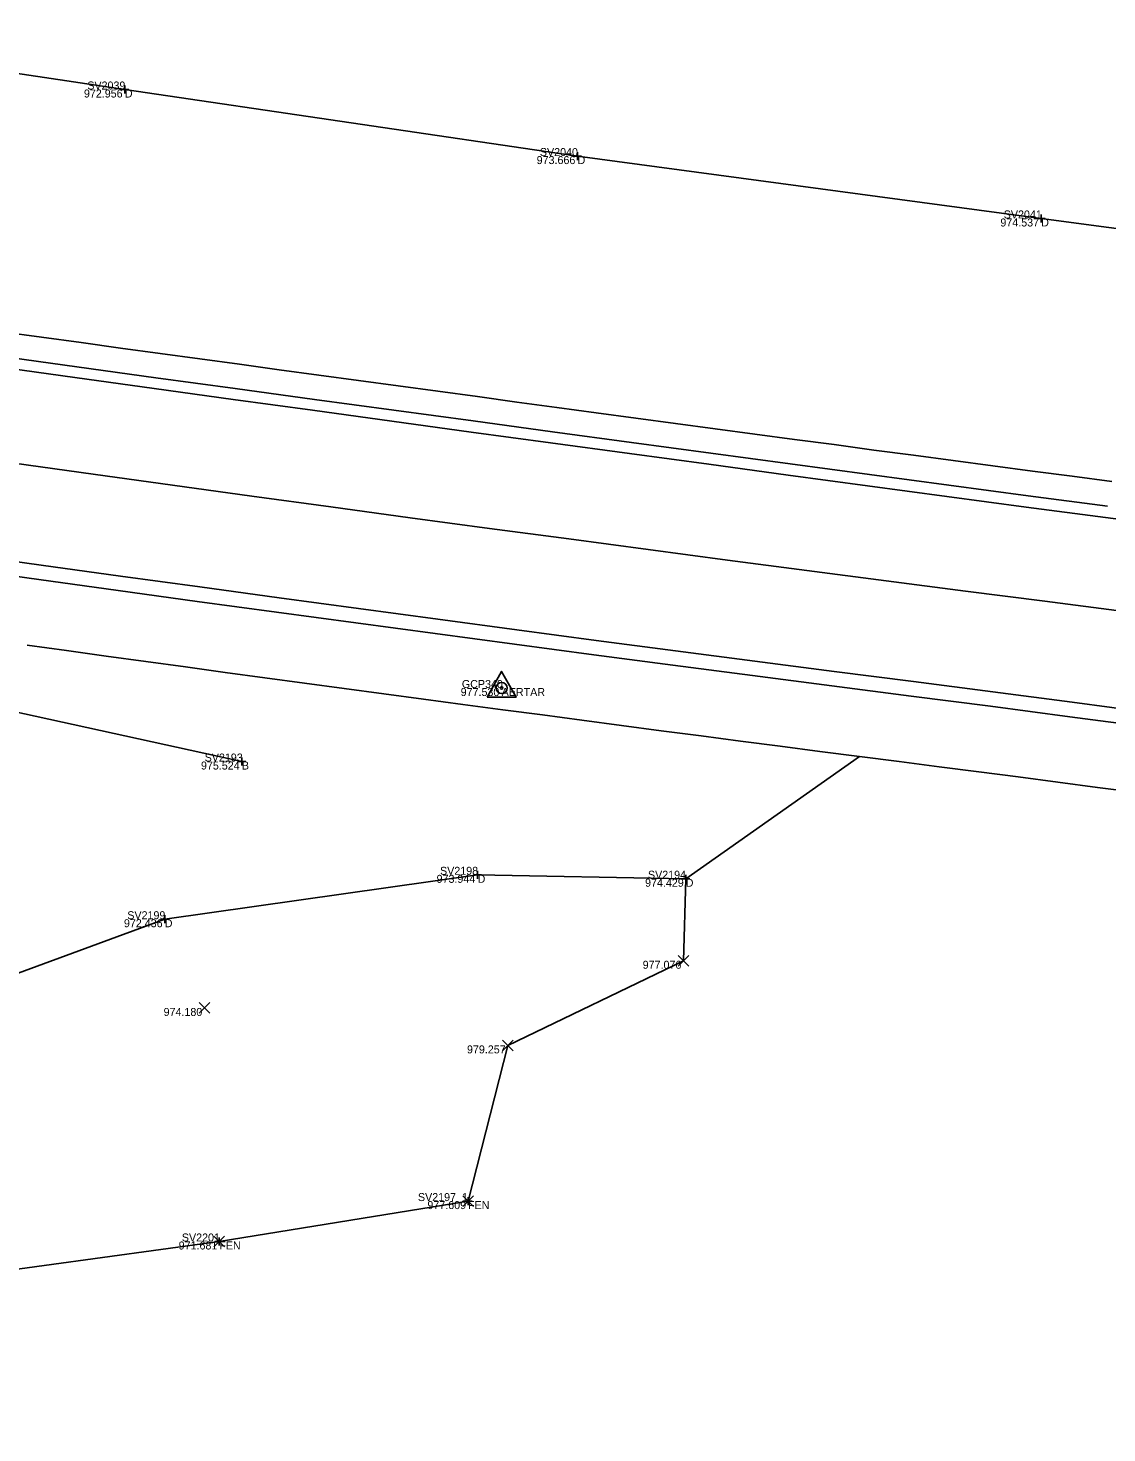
# Model space of a CAD drawing. Extents: x 2065431 to 2068157, y 709104 to 709719.
# Drawn here: x 2066585.2 to 2066720, y 709278 to 709453.6 of the extents above; entities that cross this region are included whole.
import ezdxf

# ---------------------------------------------------------------- set-up
doc = ezdxf.new("R2010")
doc.units = 0
for name, color, linetype in [('DT_X_Terrain_Boundary', 7, 'Continuous'), ('PM_X_Edge_Line', 7, 'Continuous'), ('PM_X_Lane_Line', 7, 'Continuous'), ('PV_X_EOP', 7, 'Continuous'), ('PV_X_Shoulder_Rumble_Strip', 7, 'Continuous'), ('RD_X_Fence', 7, 'Continuous'), ('RS_Raster1', 7, 'Continuous'), ('RW_X_CL_100_Bearings', 7, 'Continuous'), ('RW_X_Fee_WL', 7, 'Continuous'), ('SV_P_Aerial_Targets', 7, 'Continuous'), ('SV_X_Break_Lines', 7, 'Continuous'), ('SV_X_Mon_Cells_Found', 7, 'Continuous'), ('SV_X_Text_Elevation', 7, 'Continuous'), ('SV_X_Text_Name', 7, 'Continuous')]:
    doc.layers.add(name, color=color, linetype=linetype)

msp = doc.modelspace()

# ---------------------------------------------------------------- linework, layer by layer
at = {"layer": 'DT_X_Terrain_Boundary'}
msp.add_lwpolyline([(2066536.08, 709291.94), (2066609.07, 709301.93), (2066640.16, 709306.98), (2066645.12, 709326.44), (2066667.1, 709337.02), (2066667.37, 709347.27), (2066689.11, 709362.55), (2066694.07, 709361.91), (2066699.03, 709361.27), (2066703.99, 709360.64), (2066708.94, 709359.99), (2066713.9, 709359.34), (2066718.86, 709358.69), (2066723.82, 709358.04)], dxfattribs=at)
at = {"layer": 'PM_X_Edge_Line'}
for points in [[(2066581.1, 709411.28), (2066591.01, 709409.91), (2066600.91, 709408.54), (2066610.82, 709407.18), (2066620.73, 709405.82), (2066630.63, 709404.46), (2066640.54, 709403.11), (2066650.45, 709401.76), (2066660.36, 709400.41), (2066670.27, 709399.07), (2066680.18, 709397.72), (2066690.09, 709396.39), (2066700, 709395.05), (2066709.91, 709393.73), (2066719.82, 709392.43), (2066729.74, 709391.14)], [(2066576.92, 709387.84), (2066586.82, 709386.47), (2066596.73, 709385.1), (2066606.64, 709383.74), (2066616.55, 709382.39), (2066626.46, 709381.05), (2066636.37, 709379.71), (2066646.28, 709378.39), (2066656.19, 709377.07), (2066666.11, 709375.77), (2066676.02, 709374.47), (2066685.94, 709373.19), (2066695.86, 709371.91), (2066705.77, 709370.63), (2066715.69, 709369.33), (2066725.6, 709368.02)]]:
    msp.add_lwpolyline(points, dxfattribs=at)
at = {"layer": 'PM_X_Lane_Line'}
msp.add_lwpolyline([(2066583.41, 709399.22), (2066593.31, 709397.84), (2066603.22, 709396.47), (2066613.13, 709395.1), (2066623.03, 709393.75), (2066632.94, 709392.4), (2066642.85, 709391.06), (2066652.76, 709389.74), (2066662.68, 709388.42), (2066672.59, 709387.11), (2066682.51, 709385.81), (2066692.42, 709384.51), (2066702.34, 709383.23), (2066712.26, 709381.96), (2066722.18, 709380.69)], dxfattribs=at)
at = {"layer": 'PV_X_EOP'}
for points in [[(2066581.88, 709415.65), (2066586.83, 709414.97), (2066591.79, 709414.29), (2066596.74, 709413.61), (2066601.69, 709412.93), (2066606.65, 709412.25), (2066611.6, 709411.57), (2066616.56, 709410.9), (2066621.51, 709410.22), (2066626.46, 709409.55), (2066631.42, 709408.87), (2066636.37, 709408.2), (2066641.33, 709407.53), (2066646.28, 709406.86), (2066651.24, 709406.19), (2066656.19, 709405.52), (2066661.15, 709404.85), (2066666.1, 709404.18), (2066671.06, 709403.52), (2066676.01, 709402.85), (2066680.97, 709402.19), (2066685.93, 709401.53), (2066690.88, 709400.86), (2066695.84, 709400.2), (2066700.79, 709399.54), (2066705.75, 709398.88), (2066710.71, 709398.23), (2066715.67, 709397.58), (2066720.62, 709396.93)], [(2066585.04, 709376.47), (2066589.99, 709375.79), (2066594.94, 709375.1), (2066599.9, 709374.42), (2066604.85, 709373.74), (2066609.8, 709373.07), (2066614.76, 709372.39), (2066619.71, 709371.72), (2066624.67, 709371.05), (2066629.62, 709370.38), (2066634.58, 709369.72), (2066639.53, 709369.06), (2066644.49, 709368.39), (2066649.45, 709367.74), (2066654.4, 709367.08), (2066659.36, 709366.43), (2066664.32, 709365.77), (2066669.28, 709365.12), (2066674.23, 709364.48), (2066679.19, 709363.83), (2066684.15, 709363.19), (2066689.11, 709362.55), (2066694.07, 709361.91), (2066699.03, 709361.27), (2066703.99, 709360.64), (2066708.94, 709359.99), (2066713.9, 709359.34), (2066718.86, 709358.69), (2066723.82, 709358.04)]]:
    msp.add_lwpolyline(points, dxfattribs=at)
at = {"layer": 'PV_X_Shoulder_Rumble_Strip'}
for points in [[(2066581.34, 709412.62), (2066591.25, 709411.26), (2066601.15, 709409.9), (2066611.06, 709408.54), (2066620.97, 709407.19), (2066630.88, 709405.84), (2066640.79, 709404.49), (2066650.7, 709403.14), (2066660.61, 709401.8), (2066670.52, 709400.46), (2066680.43, 709399.13), (2066690.34, 709397.8), (2066700.25, 709396.47), (2066710.16, 709395.15), (2066720.08, 709393.85)], [(2066576.6, 709386.04), (2066586.5, 709384.66), (2066596.41, 709383.29), (2066606.31, 709381.93), (2066616.22, 709380.58), (2066626.13, 709379.24), (2066636.04, 709377.91), (2066645.96, 709376.58), (2066655.87, 709375.27), (2066665.78, 709373.96), (2066675.7, 709372.67), (2066685.62, 709371.38), (2066695.53, 709370.1), (2066705.45, 709368.83), (2066715.37, 709367.52), (2066725.28, 709366.22)]]:
    msp.add_lwpolyline(points, dxfattribs=at)
at = {"layer": 'RD_X_Fence'}
msp.add_lwpolyline([(2066428.96, 709278), (2066457.85, 709280.4), (2066536.08, 709291.94), (2066609.07, 709301.93), (2066640.16, 709306.98)], dxfattribs=at)
at = {"layer": 'RS_Raster1'}
for p, q in [((2066596.76, 709445.92), (2066597.76, 709445.92)), ((2066597.26, 709446.42), (2066597.26, 709445.42)), ((2066597.26, 709445.92), (2066597.26, 709445.92)), ((2066653.85, 709438.1), (2066653.85, 709437.1)), ((2066653.35, 709437.6), (2066654.35, 709437.6)), ((2066653.85, 709437.6), (2066653.85, 709437.6)), ((2066711.3, 709429.8), (2066712.3, 709429.8)), ((2066711.8, 709430.3), (2066711.8, 709429.3)), ((2066711.8, 709429.8), (2066711.8, 709429.8)), ((2066611.9, 709362.42), (2066611.9, 709361.42)), ((2066611.4, 709361.92), (2066612.4, 709361.92)), ((2066611.9, 709361.92), (2066611.9, 709361.92)), ((2066640.86, 709347.76), (2066641.86, 709347.76)), ((2066641.36, 709348.26), (2066641.36, 709347.26)), ((2066641.36, 709347.76), (2066641.36, 709347.76)), ((2066666.87, 709347.27), (2066667.87, 709347.27)), ((2066667.37, 709347.77), (2066667.37, 709346.77)), ((2066667.37, 709347.27), (2066667.37, 709347.27)), ((2066601.75, 709342.21), (2066602.75, 709342.21)), ((2066602.25, 709342.71), (2066602.25, 709341.71)), ((2066602.25, 709342.21), (2066602.25, 709342.21)), ((2066639.66, 709306.98), (2066640.66, 709306.98)), ((2066640.16, 709307.48), (2066640.16, 709306.48)), ((2066640.16, 709306.98), (2066640.16, 709306.98)), ((2066608.57, 709301.93), (2066609.57, 709301.93)), ((2066609.07, 709302.43), (2066609.07, 709301.43)), ((2066609.07, 709301.93), (2066609.07, 709301.93))]:
    msp.add_line(p, q, dxfattribs=at)
at = {"layer": 'RW_X_CL_100_Bearings'}
for p, q in [((2066666.43, 709336.35), (2066667.76, 709337.69)), ((2066666.43, 709337.69), (2066667.76, 709336.35)), ((2066606.56, 709330.46), (2066607.89, 709331.79)), ((2066606.56, 709331.79), (2066607.89, 709330.46)), ((2066644.46, 709325.78), (2066645.79, 709327.11)), ((2066644.46, 709327.11), (2066645.79, 709325.78)), ((2066639.49, 709306.32), (2066640.83, 709307.65)), ((2066639.49, 709307.65), (2066640.83, 709306.32)), ((2066608.4, 709301.26), (2066609.74, 709302.6)), ((2066608.4, 709302.6), (2066609.74, 709301.26))]:
    msp.add_line(p, q, dxfattribs=at)
at = {"layer": 'RW_X_Fee_WL'}
for points in [[(2066146.22, 709516.28), (2066201.46, 709507.43), (2066256.41, 709499.89), (2066309.66, 709487.73), (2066371.95, 709478.62), (2066434.46, 709468.76), (2066488.47, 709461.11), (2066543.09, 709454.02), (2066597.26, 709445.92), (2066653.85, 709437.6), (2066711.8, 709429.8), (2066769.12, 709422.19), (2066823.53, 709415.48), (2066878.43, 709408.48), (2066947.7, 709399.97)], [(2066667.37, 709347.27), (2066641.36, 709347.76), (2066602.25, 709342.21), (2066565.56, 709328.7), (2066528.33, 709316.01), (2066473.21, 709304.82), (2066473.18, 709304.77), (2066439.48, 709297.22), (2066426.74, 709291.84), (2066416.55, 709290.35)]]:
    msp.add_lwpolyline(points, dxfattribs=at)
at = {"layer": 'SV_P_Aerial_Targets'}
msp.add_lwpolyline([(2066642.56, 709369.96), (2066646.16, 709369.96), (2066644.36, 709373.18)], close=True, dxfattribs=at)
for radius in [0.7, 0.16]:
    msp.add_circle((2066644.36, 709371.11), radius, dxfattribs=at)
at = {"layer": 'SV_X_Break_Lines'}
msp.add_lwpolyline([(2066296.29, 709410.91), (2066340.48, 709404.99), (2066380.77, 709397.8), (2066419, 709392.82), (2066478.03, 709384.6), (2066527.44, 709376.82), (2066563.6, 709372.51), (2066611.9, 709361.92)], dxfattribs=at)

# ---------------------------------------------------------------- texts
at = {"layer": 'SV_X_Mon_Cells_Found'}
for s, p in [('SV2039', (2066592.57, 709445.92)), ('SV2040', (2066649.14, 709437.6)), ('SV2041', (2066707.12, 709429.8)), ('GCP340', (2066639.39, 709371.11)), ('SV2193', (2066607.24, 709361.92)), ('SV2198', (2066636.66, 709347.76)), ('SV2194', (2066662.65, 709347.27)), ('SV2199', (2066597.57, 709342.21)), ('SV2197_1', (2066633.9, 709306.98)), ('SV2201', (2066604.39, 709301.93))]:
    msp.add_text(s, height=1, dxfattribs=at).set_placement(p)
at = {"layer": 'SV_X_Text_Elevation'}
for s, p in [('D', (2066597.26, 709444.92)), ('D', (2066653.85, 709436.6)), ('D', (2066711.8, 709428.8)), ('AERTAR', (2066644.36, 709370.11)), ('B', (2066611.9, 709360.92)), ('D', (2066641.36, 709346.76)), ('D', (2066667.37, 709346.27)), ('D', (2066602.25, 709341.21)), ('FEN', (2066640.16, 709305.98)), ('FEN', (2066609.07, 709300.93))]:
    msp.add_text(s, height=1, dxfattribs=at).set_placement(p)
at = {"layer": 'SV_X_Text_Name'}
for s, p in [('972.956', (2066592.15, 709444.92)), ('973.666', (2066648.74, 709436.6)), ('974.537', (2066706.7, 709428.8)), ('977.530', (2066639.24, 709370.11)), ('975.524', (2066606.78, 709360.92)), ('973.944', (2066636.23, 709346.76)), ('974.429', (2066662.29, 709346.27)), ('972.436', (2066597.15, 709341.21)), ('977.076', (2066661.99, 709336.02)), ('974.180', (2066602.11, 709330.12)), ('979.257', (2066640.03, 709325.44)), ('977.609', (2066635.08, 709305.98)), ('977.609', (2066635.08, 709305.98)), ('971.681', (2066603.99, 709300.93)), ('971.681', (2066603.99, 709300.93))]:
    msp.add_text(s, height=1, dxfattribs=at).set_placement(p)

doc.saveas('drawing.dxf')
